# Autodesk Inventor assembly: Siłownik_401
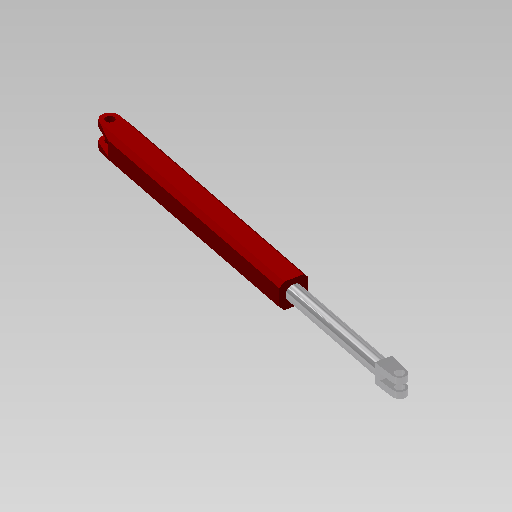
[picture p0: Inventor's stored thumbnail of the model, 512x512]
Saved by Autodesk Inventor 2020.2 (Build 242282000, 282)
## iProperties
Created: 2006-06
Part Number: Siłownik_401
Document SubType Name: Assembly
Designer: F.Stasiak
Manager: www.cadconsulting.pl
Company: Fabian Stasiak CAD Consulting
Author: F.Stasiak
Subject: Zbiór ćwiczeń. Autodesk Inventor 2020. Kurs podstawowy
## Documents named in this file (3)
- C:\2020_Kurs_podstawowy\R6 Zespoły\Adaptacyjność\Siłownik_401.iam
- C:\2020_Kurs_podstawowy\R6 Zespoły\Adaptacyjność\Cylinder_401.ipt
- C:\2020_Kurs_podstawowy\R6 Zespoły\Adaptacyjność\Tłok_401.ipt
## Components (2 placed, 2 different names)
1. Cylinder_401:1 — Zestawiające:1
2. Tłok_401:1 — Zestawiające:1
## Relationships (1: Mate 1)
- Zestawiające:1 [Mate]: Cylinder_401:1 ↔ Tłok_401:1
